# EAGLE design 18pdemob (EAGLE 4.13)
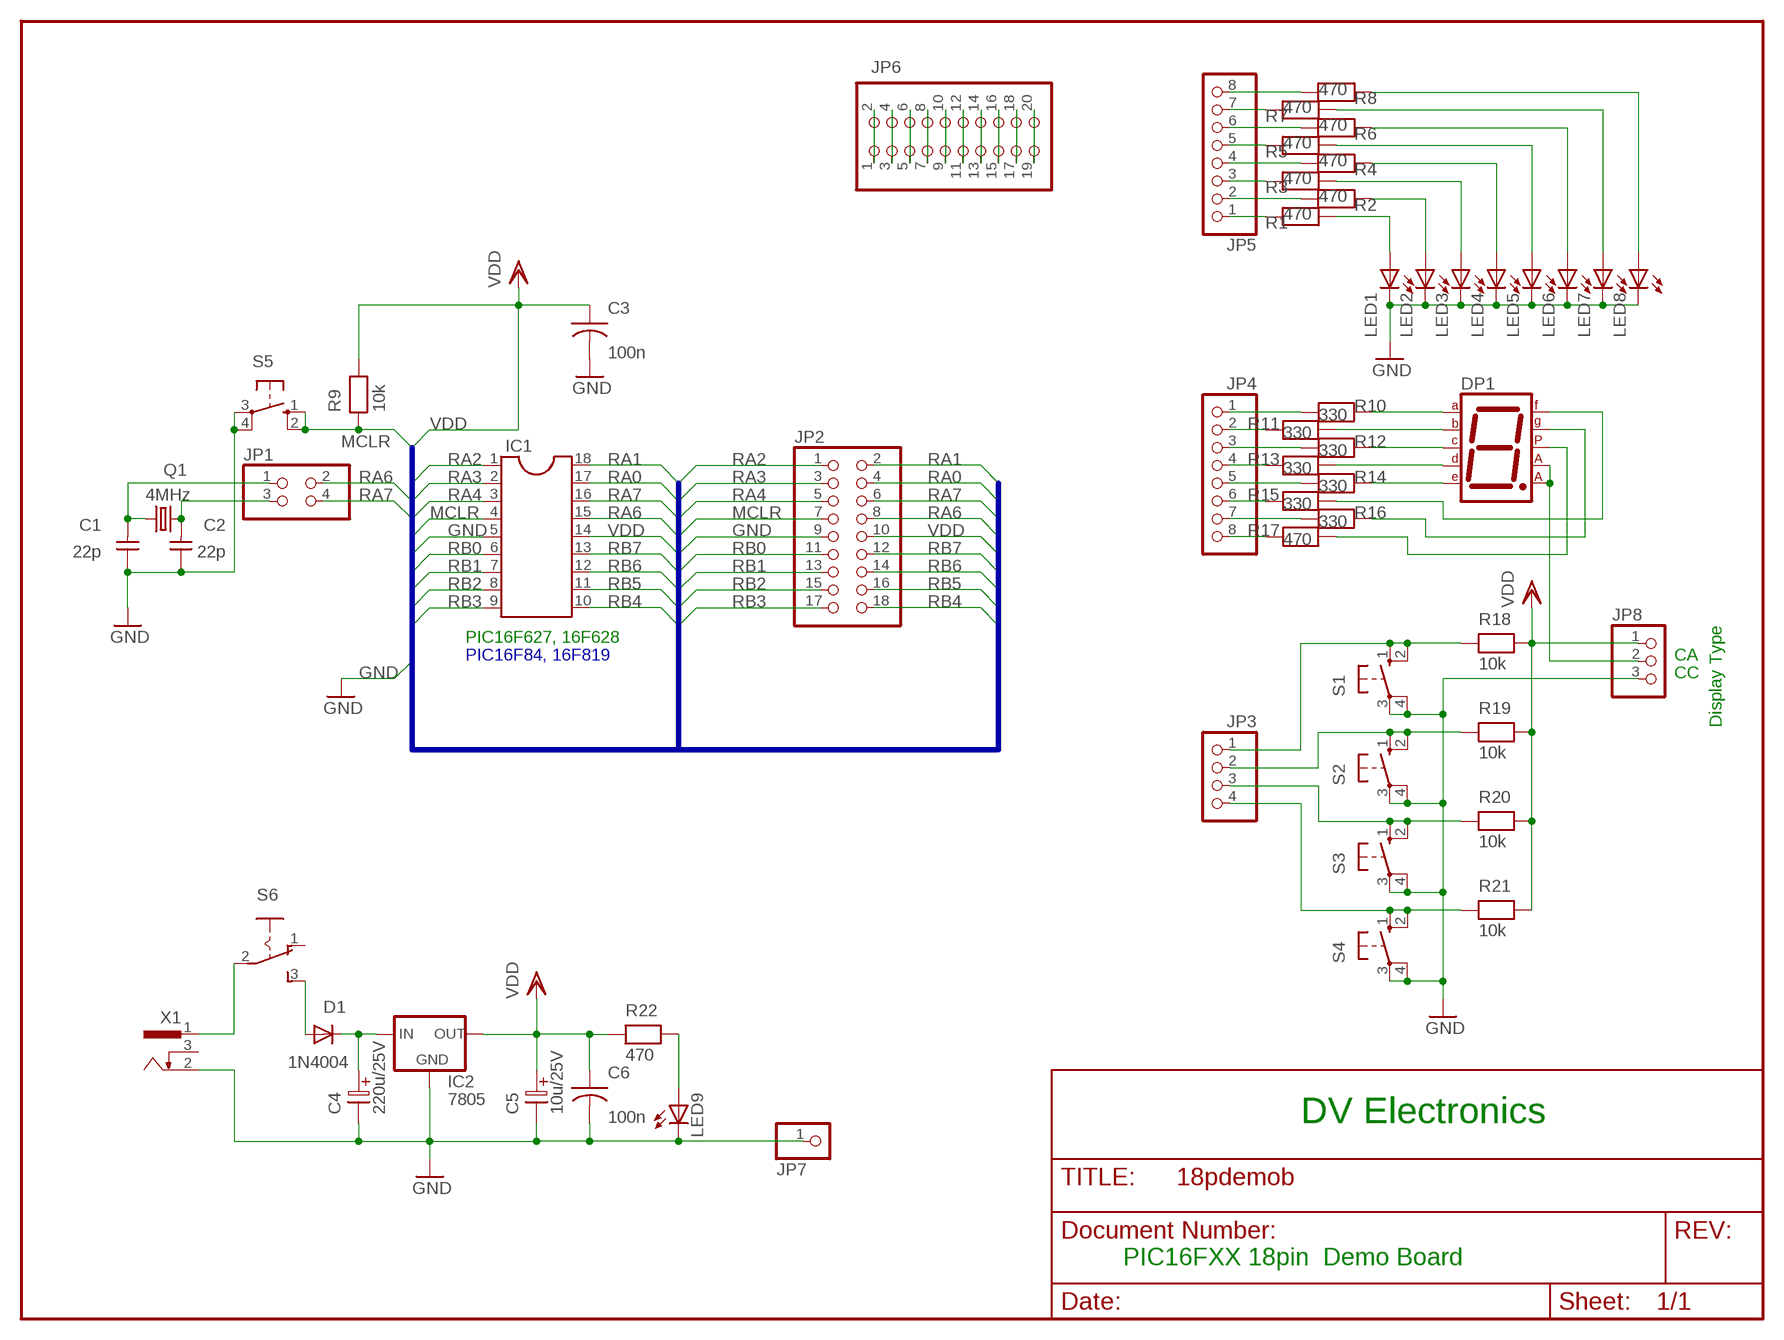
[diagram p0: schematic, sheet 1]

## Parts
C1  22p  CAPNP-5  [C-5]
C2  22p  CAPNP-5  [C-5]
C3  100n  CAP-5  [C-5]
C4  220u/25V  ELC-5  [ES-5]
C5  10u/25V  ELC-2,5L  [ES-2,5L]
C6  100n  CAP-5  [C-5]
D1  1N4004  [DO41-10]
DP1  7SEG-CA  [7SEG-13]
IC1  DIL18  [DIL18]
IC2  7805  78XXL  [78XXL]
JP1  PINHD-2X2  [2X02]
JP2  PINHD-2X9  [2X09]
JP3  PINHD-1X4  [1X04]
JP4  PINHD-1X8  [1X08]
JP5  PINHD-1X8  [1X08]
JP6  PINHD-2X10  [2X10]
JP7  PINHD-1X1  [1X01]
JP8  PINHD-1X3  [1X03]
LED1  LED3MM  [LED3MM]
LED2  LED3MM  [LED3MM]
LED3  LED3MM  [LED3MM]
LED4  LED3MM  [LED3MM]
LED5  LED3MM  [LED3MM]
LED6  LED3MM  [LED3MM]
LED7  LED3MM  [LED3MM]
LED8  LED3MM  [LED3MM]
LED9  LED3MM  [LED3MM]
Q1  4MHz  CRYTALHC49S  [HC49/S]
R1  470  RESEU-10  [R-10]
R2  470  RESEU-10  [R-10]
R3  470  RESEU-10  [R-10]
R4  470  RESEU-10  [R-10]
R5  470  RESEU-10  [R-10]
R6  470  RESEU-10  [R-10]
R7  470  RESEU-10  [R-10]
R8  470  RESEU-10  [R-10]
R9  10k  RESEU-10  [R-10]
R10  330  RESEU-7,5  [R-7,5]
R11  330  RESEU-7,5  [R-7,5]
R12  330  RESEU-7,5  [R-7,5]
R13  330  RESEU-7,5  [R-7,5]
R14  330  RESEU-7,5  [R-7,5]
R15  330  RESEU-7,5  [R-7,5]
R16  330  RESEU-7,5  [R-7,5]
R17  470  RESEU-7,5  [R-7,5]
R18  10k  RESEU-7,5  [R-7,5]
R19  10k  RESEU-7,5  [R-7,5]
R20  10k  RESEU-7,5  [R-7,5]
R21  10k  RESEU-7,5  [R-7,5]
R22  470  RESEU-7,5  [R-7,5]
S1  10-XX  [B3F-10XX]
S2  10-XX  [B3F-10XX]
S3  10-XX  [B3F-10XX]
S4  10-XX  [B3F-10XX]
S5  10-XX  [B3F-10XX]
S6  255SB  [255SB]
X1  SCD-014A  [SCD-014-A]

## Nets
GND: C1.1 C2.1 C3.2 C4.2 C5.2 C6.2 IC1.5 IC2.GND JP2.9 JP7.1 JP8.3 LED1.K(C) LED2.K(C) LED3.K(C) LED4.K(C) LED5.K(C) LED6.K(C) LED7.K(C) LED8.K(C) LED9.K(C) S1.3(P) S1.4(P1) S2.3(P) S2.4(P1) S3.3(P) S3.4(P1) S4.3(P) S4.4(P1) S5.3(P) S5.4(P1) X1.2
MCLR: IC1.4 JP2.7 R9.1 S5.1(S) S5.2(S1)
N$2: DP1.7(A) R10.2
N$3: DP1.6(B) R11.2
N$4: DP1.4(C) R12.2
N$5: DP1.2(D) R13.2
N$6: DP1.1(E) R14.2
N$7: DP1.9(F) R15.2
N$8: DP1.10(G) R16.2
N$9: LED1.A R1.2
N$10: LED2.A R2.2
N$11: LED3.A R3.2
N$12: LED4.A R4.2
N$13: LED5.A R5.2
N$14: LED6.A R6.2
N$15: LED7.A R7.2
N$16: LED8.A R8.2
N$20: C2.2 JP1.3 Q1.2
N$22: C1.2 JP1.1 Q1.1
N$24: JP5.8 R8.1
N$34: S6.2(P) X1.1
N$35: C4.1 D1.C IC2.IN
N$38: DP1.5(DP) R17.2
N$39: JP6.1 JP6.2
N$40: JP4.7 R16.1
N$41: JP4.5 R14.1
N$42: JP4.3 R12.1
N$43: JP4.1 R10.1
N$44: JP4.2 R11.1
N$45: JP4.4 R13.1
N$46: JP4.6 R15.1
N$47: JP4.8 R17.1
N$48: JP5.7 R7.1
N$49: JP5.6 R6.1
N$50: JP5.5 R5.1
N$51: JP5.4 R4.1
N$52: JP5.3 R3.1
N$53: JP5.2 R2.1
N$54: JP5.1 R1.1
N$220: DP1.3(CA1) DP1.8(CA2) JP8.2
N$383: LED9.A R22.2
N$384: JP3.1 R18.1 S1.1(S) S1.2(S1)
N$385: JP3.2 R19.1 S2.1(S) S2.2(S1)
N$386: JP3.3 R20.1 S3.1(S) S3.2(S1)
N$387: JP3.4 R21.1 S4.1(S) S4.2(S1)
N$390: JP6.3 JP6.4
N$391: JP6.5 JP6.6
N$392: JP6.7 JP6.8
N$393: JP6.9 JP6.10
N$394: JP6.11 JP6.12
N$395: JP6.13 JP6.14
N$396: JP6.15 JP6.16
N$397: JP6.17 JP6.18
N$398: JP6.19 JP6.20
N$399: D1.A S6.3(S)
RA0: IC1.17 JP2.4
RA1: IC1.18 JP2.2
RA2: IC1.1 JP2.1
RA3: IC1.2 JP2.3
RA4: IC1.3 JP2.5
RA6: IC1.15 JP1.2 JP2.8
RA7: IC1.16 JP1.4 JP2.6
RB0: IC1.6 JP2.11
RB1: IC1.7 JP2.13
RB2: IC1.8 JP2.15
RB3: IC1.9 JP2.17
RB4: IC1.10 JP2.18
RB5: IC1.11 JP2.16
RB6: IC1.12 JP2.14
RB7: IC1.13 JP2.12
VDD: C3.1 C5.1 C6.1 IC1.14 IC2.OUT JP2.10 JP8.1 R9.2 R18.2 R19.2 R20.2 R21.2 R22.1
Unconnected: S6.1(O) X1.3

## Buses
B$1

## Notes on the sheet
- Display Type
- PIC16F627, 16F628
- PIC16F84, 16F819 | CA
- CC
- DV Electronics
- PIC16FXX 18pin  Demo Board

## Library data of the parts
C1 C2 = discrete:CAPNP-5
C3 C6 = discrete:CAP-5
C4 = discrete:ELC-5
C5 = discrete:ELC-2,5L
D1 = diode:1N4004: DIODE
DP1 = special:7SEG-CA: 7-segment DISPLAY single anode, 13 mm
IC1 = ic-package:DIL18: Dual In Line
IC2 = v-reg:78XXL: VOLTAGE REGULATOR
JP1 = pinhead:PINHD-2X2: PIN HEADER
JP2 = pinhead:PINHD-2X9: PIN HEADER
JP3 = pinhead:PINHD-1X4: PIN HEADER
JP4 JP5 = pinhead:PINHD-1X8: PIN HEADER
JP6 = pinhead:PINHD-2X10: PIN HEADER
JP7 = pinhead:PINHD-1X1: PIN HEADER
JP8 = pinhead:PINHD-1X3: PIN HEADER
LED1-LED9 = led:LED: LED
Q1 = crystal:CRYTAL: CRYSTAL
R1-R9 = discrete:RESEU-10
R10-R22 = discrete:RESEU-7,5
S1-S5 = switch-omron:10-XX: OMRON SWITCH
S6 = switch:255SB: SLIDING SWITCH distributor Buerklin, 11G810
X1 = con-shiua-chyuan:SCD-014A: Power Jack 2.5mm

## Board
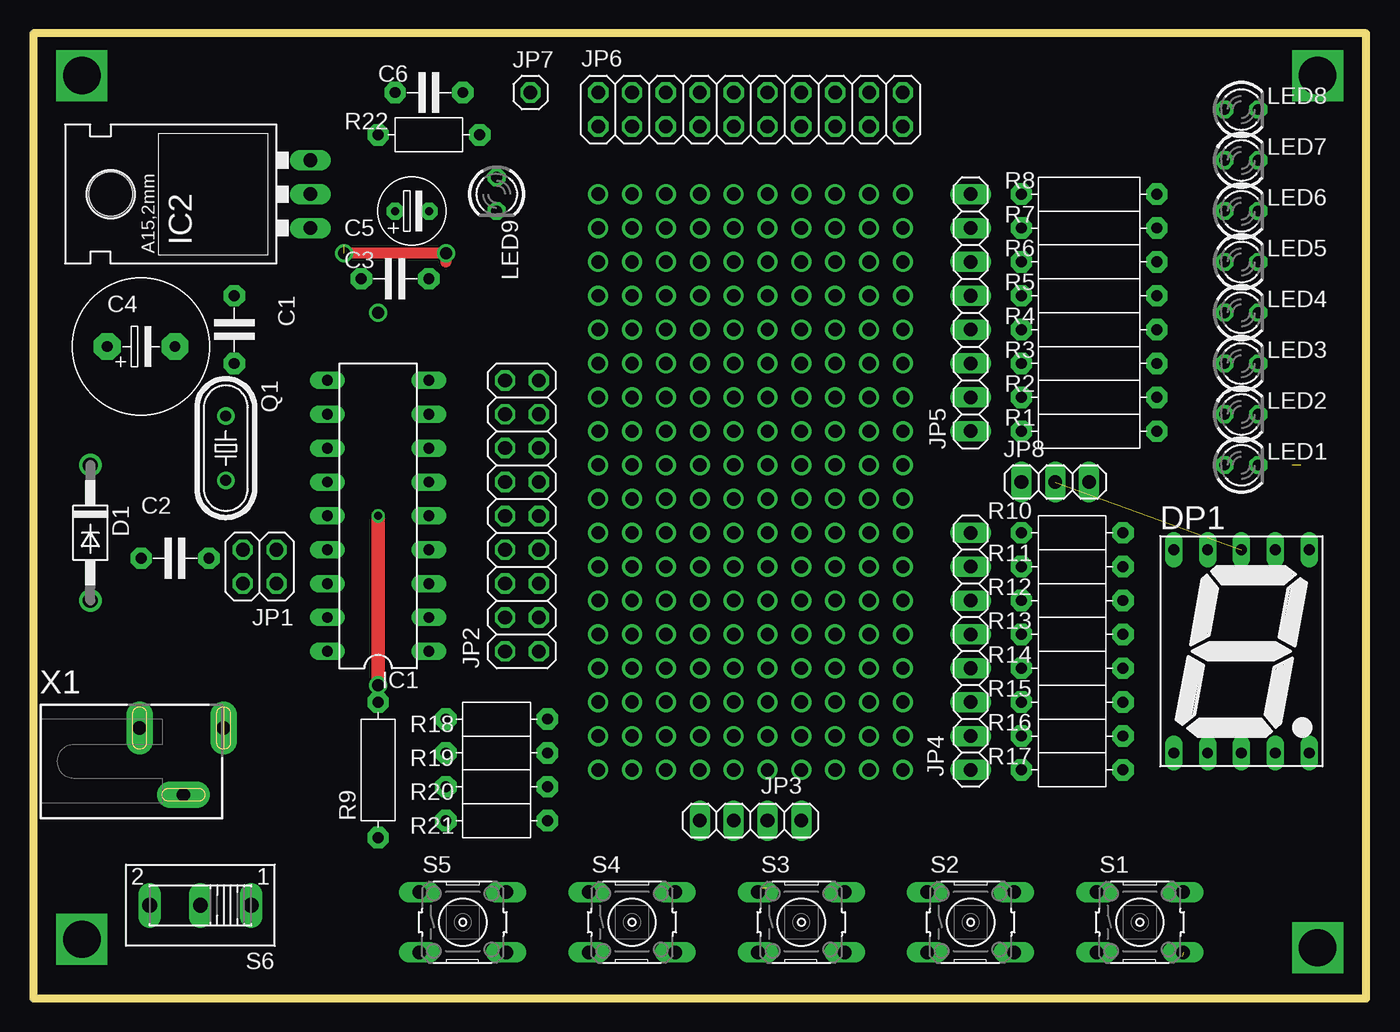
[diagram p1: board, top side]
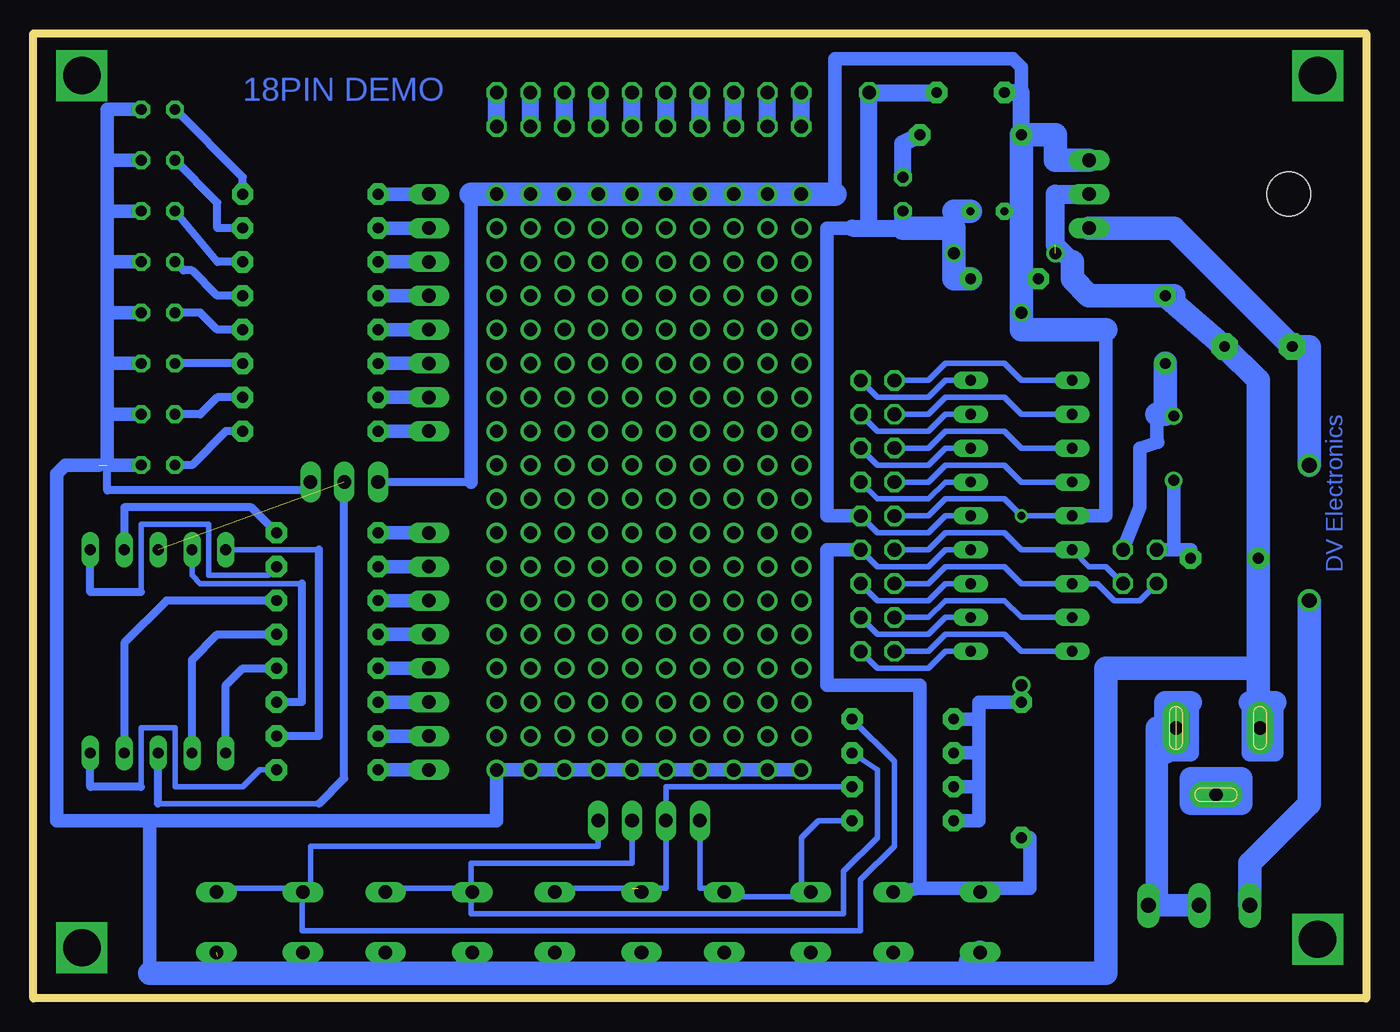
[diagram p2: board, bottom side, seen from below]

Size 100 x 72.38 mm. Coordinates in mm from the lower left corner, seen from the top.
Outline: 0,0 100,0 100,72.38 0,72.38 0,0
Copper layers (1*16): Top 0.035mm / dielectric 1.5mm / Bottom 0.035mm
Design rules "default": minimum track width 10mil, minimum drill 24mil, track to track 8mil, track to pad 8mil, pad to pad 8mil, via to via 8mil, smd to smd 8mil, copper to edge 40mil, drill to drill 8mil, minimum pad ring 10mil, minimum via ring 8mil, stop-mask expansion 4mil, vias tented up to drill 0mil, thermal gap 10mil

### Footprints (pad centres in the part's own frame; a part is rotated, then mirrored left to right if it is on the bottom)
C-5 = drill 0.813 pad 1.6 octagon: 1 -2.54,0; 2 2.54,0
ES-5 = drill 0.813 pad 2.007 octagon: 1 -2.54,0; 2 2.54,0
ES-2,5L = drill 0.61 pad 1.27 octagon: 1 0,0; 2 2.54,0
DO41-10 = drill 1.118 round: A 5.08,0; C -5.08,0
7SEG-13 = drill 0.813 long: 1 -5.08,-7.62; 2 -2.54,-7.62; 3 0,-7.62; 4 2.54,-7.62; 5 5.08,-7.62; 6 5.08,7.62; 7 2.54,7.62; 8 0,7.62; 9 -2.54,7.62; 10 -5.08,7.62
DIL18 = drill 0.813 long: 1 -10.16,-3.81; 2 -7.62,-3.81; 3 -5.08,-3.81; 4 -2.54,-3.81; 5 0,-3.81; 6 2.54,-3.81; 7 5.08,-3.81; 8 7.62,-3.81; 9 10.16,-3.81; 10 10.16,3.81; 11 7.62,3.81; 12 5.08,3.81; 13 2.54,3.81; 14 0,3.81; 15 -2.54,3.81; 16 -5.08,3.81; 17 -7.62,3.81; 18 -10.16,3.81
78XXL = drill 1.016 long: GND 0,-3.81; IN -2.54,-3.81; OUT 2.54,-3.81 | hole 3.302: 0,11.176
2X02 = drill 1.016 octagon: 1 -1.27,-1.27; 2 -1.27,1.27; 3 1.27,-1.27; 4 1.27,1.27
2X09 = drill 1.016 octagon: 1 -10.16,-1.27; 2 -10.16,1.27; 3 -7.62,-1.27; 4 -7.62,1.27; 5 -5.08,-1.27; 6 -5.08,1.27; 7 -2.54,-1.27; 8 -2.54,1.27; 9 0,-1.27; 10 0,1.27; 11 2.54,-1.27; 12 2.54,1.27; 13 5.08,-1.27; 14 5.08,1.27; 15 7.62,-1.27; 16 7.62,1.27; 17 10.16,-1.27; 18 10.16,1.27
1X04 = drill 1.016 long: 1 -3.81,0; 2 -1.27,0; 3 1.27,0; 4 3.81,0
1X08 = drill 1.016 long: 1 -8.89,0; 2 -6.35,0; 3 -3.81,0; 4 -1.27,0; 5 1.27,0; 6 3.81,0; 7 6.35,0; 8 8.89,0
2X10 = drill 1.016 octagon: 1 -11.43,-1.27; 2 -11.43,1.27; 3 -8.89,-1.27; 4 -8.89,1.27; 5 -6.35,-1.27; 6 -6.35,1.27; 7 -3.81,-1.27; 8 -3.81,1.27; 9 -1.27,-1.27; 10 -1.27,1.27; 11 1.27,-1.27; 12 1.27,1.27; 13 3.81,-1.27; 14 3.81,1.27; 15 6.35,-1.27; 16 6.35,1.27; 17 8.89,-1.27; 18 8.89,1.27; 19 11.43,-1.27; 20 11.43,1.27
1X01 = drill 1.016 octagon: 1 0,0
1X03 = drill 1.016 long: 1 -2.54,0; 2 0,0; 3 2.54,0
LED3MM = drill 0.813 octagon: A -1.27,0; K 1.27,0
HC49/S = drill 0.813 round: 1 -2.413,0; 2 2.413,0
R-10 = drill 0.813 pad 1.6 octagon: 1 -5.08,0; 2 5.08,0
R-7,5 = drill 0.813 pad 1.6 octagon: 1 -3.81,0; 2 3.81,0
B3F-10XX = drill 1.016 long: 1 -3.251,2.261; 2 3.251,2.261; 3 -3.251,-2.261; 4 3.251,-2.261
255SB = drill 1.118 long: 1 -3.81,0; 2 0,0; 3 3.81,0
SCD-014-A = drill 1 pad 2 long: 1 -2.5,13.8; 2 -2.5,7.5; 3 2.5,10.8

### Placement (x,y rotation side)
C1  15.08,50.16 270 top
C2  10.63,33.02 0 top
C3  27.14,53.97 0 top
C4  8.09,48.89 0 top
C5  27.14,59.05 0 top
C6  29.68,67.94 0 top
D1  4.28,34.92 270 top
DP1  90.64,26.03 0 top
IC1  25.87,36.19 90 top
IC2  16.98,60.32 90 top
JP1  16.98,32.38 180 top
JP2  36.66,36.19 90 top
JP3  53.81,13.33 180 top
JP4  70.32,26.03 270 top
JP5  70.32,51.43 90 top
JP6  53.81,66.67 0 top
JP7  37.3,67.94 0 top
JP8  76.67,38.73 0 top
LED1  90.64,40 0 top
LED2  90.64,43.81 0 top
LED3  90.64,47.62 0 top
LED4  90.64,51.43 0 top
LED5  90.64,55.24 0 top
LED6  90.64,59.05 0 top
LED7  90.64,62.86 0 top
LED8  90.64,66.67 0 top
LED9  34.76,60.32 270 top
Q1  14.44,41.27 270 top
R1  79.21,42.54 0 top
R2  79.21,45.08 0 top
R3  79.21,47.62 0 top
R4  79.21,50.16 0 top
R5  79.21,52.7 0 top
R6  79.21,55.24 0 top
R7  79.21,57.78 0 top
R8  79.21,60.32 0 top
R9  25.87,17.14 90 top
R10  77.94,34.92 0 top
R11  77.94,32.38 0 top
R12  77.94,29.84 0 top
R13  77.94,27.3 0 top
R14  77.94,24.76 0 top
R15  77.94,22.22 0 top
R16  77.94,19.68 0 top
R17  77.94,17.14 0 top
R18  34.76,20.95 180 top
R19  34.76,18.41 180 top
R20  34.76,15.87 180 top
R21  34.76,13.33 180 top
R22  29.68,64.77 0 top
S1  83.02,5.71 0 top
S2  70.32,5.71 0 top
S3  57.62,5.71 0 top
S4  44.92,5.71 0 top
S5  32.22,5.71 0 top
S6  12.54,6.98 180 top
X1  0.47,17.77 270 top

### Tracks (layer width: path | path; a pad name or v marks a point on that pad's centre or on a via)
GND  (via drill 0.9, 1)  (3 unrouted)
  Top 0.813: 30.95,55.24 v30.95,55.88 v23.33,55.88
  Bottom 0.406: 30.95,57.78 30.95,59.05 | IC1.5 31.58,36.19 32.85,34.92 36.66,34.92 JP2.9
  Bottom 0.61: JP8.3 79.84,38.1 94.45,38.1 94.45,40
  Bottom 1.016: 86.83,3.17 85.56,1.9 86.19,2.54 86.19,3.17 | S1.3 80.48,2.74 80.48,1.9 | S2.4 74.13,2.89 74.13,1.9 | S2.3 67.78,2.74 67.78,1.9 | S3.4 61.43,2.89 61.43,1.9 | S3.3 55.08,2.74 55.08,1.9 | S4.4 48.73,2.89 48.73,1.9 | S4.3 42.38,2.74 42.38,1.9 | S5.4 36.03,2.89 36.03,1.9 | 29.68,1.9 29.68,2.74 | v42.38,17.14 v65.24,17.14 65.24,13.33 91.28,13.33 | 91.28,1.9 91.28,13.33 | 91.28,13.33 98.26,13.33 98.26,39.37 97.62,40 95.08,40 | LED8.K 94.45,66.67 94.45,62.86 | 94.45,43.81 94.45,40 LED1.K | 94.45,43.81 94.45,47.62 | 94.45,47.62 94.45,51.43 | 94.45,51.43 94.45,55.24 | 94.45,55.24 94.45,59.05 | 94.45,59.05 94.45,62.86 | 94.45,62.86 LED7.K | 94.45,59.05 LED6.K | 94.45,55.24 LED5.K | 94.45,51.43 LED4.K | 94.45,47.62 LED3.K | 94.45,43.81 LED2.K | JP2.9 40.48,36.19 40.48,57.78 38.57,57.78
  Bottom 1.27: 37.3,57.78 JP7.1 C6.2 | 37.3,57.78 34.76,57.78 LED9.K | 38.57,57.78 37.3,57.78
  Bottom 1.422: C4.2 C1.1 | 22.06,55.24 23.33,56.51 23.33,60.32 IC2.GND
  Bottom 1.676: X1.2 8.09,20.27 8.09,20.31 8.09,19.68
  Bottom 1.778: 34.76,57.78 30.95,57.78 v30.95,55.88 30.95,53.97 C3.2 | 30.95,59.05 C5.2 | C1.1 14.44,52.7 | C1.1 20.79,52.7 22.06,53.97 22.06,55.24 | 29.68,2.74 S5.3 | 91.28,1.9 85.56,1.9 80.48,1.9 74.13,1.9 67.78,1.9 61.43,1.9 55.08,1.9 48.73,1.9 42.38,1.9 36.03,1.9 29.68,1.9 19.52,1.9 19.52,24.76 8.09,24.76 | 8.09,24.76 C2.1 8.09,46.35 C4.2 C1.1 | 8.09,24.76 8.09,20.31
MCLR
  Bottom 0.406: JP2.7 36.66,32.38 32.85,32.38 31.58,33.65 IC1.4 | 25.23,8.25 33.49,8.25
  Bottom 1.016: 33.49,8.25 S5.2 | 33.49,8.25 29.04,8.25 S5.1 28.69,8.25 25.23,8.25 25.23,12.06 R9.1 | JP2.7 40.48,33.65 40.48,23.49 33.49,23.49 33.49,8.25
N$1  (via drill 1)
  other vias: 42.38,60.32
N$2
  Bottom 0.61: DP1.7 93.18,36.83 83.66,36.83 R10.2
N$3
  Bottom 0.406: R11.2 82.39,31.74 86.83,31.74 86.83,35.55 91.91,35.55 91.91,30.47
  Bottom 0.61: 91.91,30.47 95.72,30.47 DP1.6
N$4
  Bottom 0.61: DP1.4 93.18,26.66 90,29.84 R12.2
N$5
  Bottom 0.61: R13.2 86.19,27.3 88.1,25.39 DP1.2
N$6
  Bottom 0.61: R14.2 84.29,24.76 85.56,23.49 DP1.1
N$7
  Bottom 0.406: DP1.9 88.1,31.74 87.47,31.11 79.84,31.11
  Bottom 0.61: 79.84,31.11 79.84,22.22 R15.2
N$8
  Bottom 0.406: 78.58,33.65 DP1.10
  Bottom 0.61: R16.2 78.58,19.68 78.58,33.65
N$9
  Bottom 0.61: LED1.A 88.1,40 85.56,42.54 R1.2
N$10
  Bottom 0.61: LED2.A 87.47,43.81 86.19,45.08 R2.2
N$11
  Bottom 0.61: R3.2 LED3.A
N$12
  Bottom 0.61: LED4.A 87.47,51.43 86.19,50.16 R4.2
N$13
  Bottom 0.61: LED5.A 88.73,54.61 88.1,54.61 86.19,52.7 R5.2
N$14
  Bottom 0.61: LED6.A 86.19,55.24 R6.2
N$15
  Bottom 0.61: LED7.A 86.19,59.69 86.19,57.78 R7.2
N$16
  Bottom 0.61: LED8.A 84.29,61.59 R8.2
N$17  (via drill 1)
  other vias: 44.92,60.32
N$18  (via drill 1)
  other vias: 47.46,60.32
N$19  (via drill 1)
  other vias: 50,60.32
N$20
  Bottom 0.406: JP1.3 14.44,33.65
  Bottom 1.016: 14.44,33.65 Q1.2 | JP1.3 13.17,33.65 C2.2
N$21  (via drill 1)
  other vias: 52.54,60.32
N$22
  Bottom 0.406: 14.44,43.81 Q1.1 | 15.65,41.71 15.71,41.91
  Bottom 1.016: JP1.1 16.98,36.83 16.98,41.27 15.65,41.71 | 15.71,41.91 15.71,43.81 14.44,43.81
  Bottom 1.778: 15.71,43.81 15.08,43.81 C1.2
N$23  (via drill 1)
  other vias: 55.08,60.32
N$24
  Bottom 1.016: JP5.8 R8.1
N$25  (via drill 1)
  other vias: 57.62,60.32
N$26  (via drill 1)
  other vias: 60.16,60.32
N$27  (via drill 1)
  other vias: 62.7,60.32
N$28  (via drill 1)
  other vias: 65.24,60.32
N$29  (via drill 1)
  other vias: 42.38,57.78
N$30  (via drill 1)
  other vias: 44.92,57.78
N$31  (via drill 1)
  other vias: 47.46,57.78
N$32  (via drill 1)
  other vias: 50,57.78
N$33  (via drill 1)
  other vias: 52.54,57.78
N$34
  Bottom 1.676: S6.2 15.71,6.98 15.71,20.27 | X1.1 15.71,20.27 | 15.71,20.27 15.71,20.31
N$35
  Bottom 1.778: IC2.IN 14.44,57.78 C4.1 4.28,48.89 D1.C
N$36  (via drill 1)
  other vias: 55.08,57.78
N$37  (via drill 1)
  other vias: 57.62,57.78
N$38
  Bottom 0.406: 91.91,15.87 91.91,20.31 89.37,20.31 89.37,15.87 84.29,15.87 83.02,17.14 R17.2
  Bottom 0.61: DP1.5 95.72,15.87 91.91,15.87
N$39
  Bottom 1.27: JP6.1 JP6.2
N$40
  Bottom 1.016: JP4.7 R16.1
N$41
  Bottom 1.016: JP4.5 R14.1
N$42
  Bottom 1.016: JP4.3 R12.1
N$43
  Bottom 1.016: JP4.1 R10.1
N$44
  Bottom 1.016: JP4.2 R11.1
N$45
  Bottom 1.016: JP4.4 R13.1
N$46
  Bottom 1.016: JP4.6 R15.1
N$47
  Bottom 1.016: JP4.8 R17.1
N$48
  Bottom 1.016: JP5.7 R7.1
N$49
  Bottom 1.016: JP5.6 R6.1
N$50
  Bottom 1.016: JP5.5 R5.1
N$51
  Bottom 1.016: JP5.4 R4.1
N$52
  Bottom 1.016: JP5.3 R3.1
N$53
  Bottom 1.016: JP5.2 R2.1
N$54
  Bottom 1.016: JP5.1 R1.1
N$55  (via drill 1)
  other vias: 60.16,57.78
N$56  (via drill 1)
  other vias: 62.7,57.78
N$57  (via drill 1)
  other vias: 65.24,57.78
N$58  (via drill 1)
  other vias: 42.38,55.24
N$59  (via drill 1)
  other vias: 44.92,55.24
N$60  (via drill 1)
  other vias: 47.46,55.24
N$61  (via drill 1)
  other vias: 50,55.24
N$62  (via drill 1)
  other vias: 52.54,55.24
N$63  (via drill 1)
  other vias: 55.08,55.24
N$64  (via drill 1)
  other vias: 57.62,55.24
N$65  (via drill 1)
  other vias: 60.16,55.24
N$66  (via drill 1)
  other vias: 62.7,55.24
N$67  (via drill 1)
  other vias: 65.24,55.24
N$68  (via drill 1)
  other vias: 42.38,52.7
N$69  (via drill 1)
  other vias: 44.92,52.7
N$70  (via drill 1)
  other vias: 47.46,52.7
N$71  (via drill 1)
  other vias: 50,52.7
N$72  (via drill 1)
  other vias: 52.54,52.7
N$73  (via drill 1)
  other vias: 55.08,52.7
N$74  (via drill 1)
  other vias: 57.62,52.7
N$75  (via drill 1)
  other vias: 60.16,52.7
N$76  (via drill 1)
  other vias: 62.7,52.7
N$77  (via drill 1)
  other vias: 65.24,52.7
N$78  (via drill 1)
  other vias: 42.38,50.16
N$79  (via drill 1)
  other vias: 44.92,50.16
N$80  (via drill 1)
  other vias: 47.46,50.16
N$81  (via drill 1)
  other vias: 50,50.16
N$82  (via drill 1)
  other vias: 52.54,50.16
N$83  (via drill 1)
  other vias: 55.08,50.16
N$84  (via drill 1)
  other vias: 57.62,50.16
N$85  (via drill 1)
  other vias: 60.16,50.16
N$86  (via drill 1)
  other vias: 62.7,50.16
N$87  (via drill 1)
  other vias: 65.24,50.16
N$88  (via drill 1)
  other vias: 42.38,47.62
N$89  (via drill 1)
  other vias: 44.92,47.62
N$90  (via drill 1)
  other vias: 47.46,47.62
N$91  (via drill 1)
  other vias: 50,47.62
N$92  (via drill 1)
  other vias: 52.54,47.62
N$93  (via drill 1)
  other vias: 55.08,47.62
N$94  (via drill 1)
  other vias: 57.62,47.62
N$95  (via drill 1)
  other vias: 60.16,47.62
N$96  (via drill 1)
  other vias: 62.7,47.62
N$97  (via drill 1)
  other vias: 65.24,47.62
N$98  (via drill 1)
  other vias: 42.38,45.08
N$99  (via drill 1)
  other vias: 44.92,45.08
N$100  (via drill 1)
  other vias: 47.46,45.08
N$101  (via drill 1)
  other vias: 50,45.08
N$102  (via drill 1)
  other vias: 52.54,45.08
N$103  (via drill 1)
  other vias: 55.08,45.08
N$104  (via drill 1)
  other vias: 57.62,45.08
N$105  (via drill 1)
  other vias: 60.16,45.08
N$106  (via drill 1)
  other vias: 62.7,45.08
N$107  (via drill 1)
  other vias: 65.24,45.08
N$108  (via drill 1)
  other vias: 42.38,42.54
N$109  (via drill 1)
  other vias: 44.92,42.54
N$110  (via drill 1)
  other vias: 47.46,42.54
N$111  (via drill 1)
  other vias: 50,42.54
N$112  (via drill 1)
  other vias: 52.54,42.54
N$113  (via drill 1)
  other vias: 55.08,42.54
N$114  (via drill 1)
  other vias: 57.62,42.54
N$115  (via drill 1)
  other vias: 60.16,42.54
N$116  (via drill 1)
  other vias: 62.7,42.54
N$117  (via drill 1)
  other vias: 65.24,42.54
N$118  (via drill 1)
  other vias: 42.38,40
N$119  (via drill 1)
  other vias: 44.92,40
N$120  (via drill 1)
  other vias: 47.46,40
N$121  (via drill 1)
  other vias: 50,40
N$122  (via drill 1)
  other vias: 52.54,40
N$123  (via drill 1)
  other vias: 55.08,40
N$124  (via drill 1)
  other vias: 57.62,40
N$125  (via drill 1)
  other vias: 60.16,40
N$126  (via drill 1)
  other vias: 62.7,40
N$127  (via drill 1)
  other vias: 65.24,40
N$128  (via drill 1)
  other vias: 42.38,37.46
N$129  (via drill 1)
  other vias: 44.92,37.46
N$130  (via drill 1)
  other vias: 47.46,37.46
N$131  (via drill 1)
  other vias: 50,37.46
N$132  (via drill 1)
  other vias: 52.54,37.46
N$133  (via drill 1)
  other vias: 55.08,37.46
N$134  (via drill 1)
  other vias: 57.62,37.46
N$135  (via drill 1)
  other vias: 60.16,37.46
N$136  (via drill 1)
  other vias: 62.7,37.46
N$137  (via drill 1)
  other vias: 65.24,37.46
N$138  (via drill 1)
  other vias: 42.38,34.92
N$139  (via drill 1)
  other vias: 44.92,34.92
N$140  (via drill 1)
  other vias: 47.46,34.92
N$141  (via drill 1)
  other vias: 50,34.92
N$142  (via drill 1)
  other vias: 52.54,34.92
N$143  (via drill 1)
  other vias: 55.08,34.92
N$144  (via drill 1)
  other vias: 57.62,34.92
N$145  (via drill 1)
  other vias: 60.16,34.92
N$146  (via drill 1)
  other vias: 62.7,34.92
N$147  (via drill 1)
  other vias: 65.24,34.92
N$148  (via drill 1)
  other vias: 42.38,32.38
N$149  (via drill 1)
  other vias: 44.92,32.38
N$150  (via drill 1)
  other vias: 47.46,32.38
N$151  (via drill 1)
  other vias: 50,32.38
N$152  (via drill 1)
  other vias: 52.54,32.38
N$153  (via drill 1)
  other vias: 55.08,32.38
N$154  (via drill 1)
  other vias: 57.62,32.38
N$155  (via drill 1)
  other vias: 60.16,32.38
N$156  (via drill 1)
  other vias: 62.7,32.38
N$157  (via drill 1)
  other vias: 65.24,32.38
N$158  (via drill 1)
  other vias: 42.38,29.84
N$159  (via drill 1)
  other vias: 44.92,29.84
N$160  (via drill 1)
  other vias: 47.46,29.84
N$161  (via drill 1)
  other vias: 50,29.84
N$162  (via drill 1)
  other vias: 52.54,29.84
N$163  (via drill 1)
  other vias: 55.08,29.84
N$164  (via drill 1)
  other vias: 57.62,29.84
N$165  (via drill 1)
  other vias: 60.16,29.84
N$166  (via drill 1)
  other vias: 62.7,29.84
N$167  (via drill 1)
  other vias: 65.24,29.84
N$168  (via drill 1)
  other vias: 42.38,27.3
N$169  (via drill 1)
  other vias: 44.92,27.3
N$170  (via drill 1)
  other vias: 47.46,27.3
N$171  (via drill 1)
  other vias: 50,27.3
N$172  (via drill 1)
  other vias: 52.54,27.3
N$173  (via drill 1)
  other vias: 55.08,27.3
N$174  (via drill 1)
  other vias: 57.62,27.3
N$175  (via drill 1)
  other vias: 60.16,27.3
N$176  (via drill 1)
  other vias: 62.7,27.3
N$177  (via drill 1)
  other vias: 65.24,27.3
N$178  (via drill 1)
  other vias: 42.38,24.76
N$179  (via drill 1)
  other vias: 44.92,24.76
N$180  (via drill 1)
  other vias: 47.46,24.76
N$181  (via drill 1)
  other vias: 50,24.76
N$182  (via drill 1)
  other vias: 52.54,24.76
N$183  (via drill 1)
  other vias: 55.08,24.76
N$184  (via drill 1)
  other vias: 57.62,24.76
N$185  (via drill 1)
  other vias: 60.16,24.76
N$186  (via drill 1)
  other vias: 62.7,24.76
N$187  (via drill 1)
  other vias: 65.24,24.76
N$188  (via drill 1)
  other vias: 42.38,22.22
N$189  (via drill 1)
  other vias: 44.92,22.22
N$190  (via drill 1)
  other vias: 47.46,22.22
N$191  (via drill 1)
  other vias: 50,22.22
N$192  (via drill 1)
  other vias: 52.54,22.22
N$193  (via drill 1)
  other vias: 55.08,22.22
N$194  (via drill 1)
  other vias: 57.62,22.22
N$195  (via drill 1)
  other vias: 60.16,22.22
N$196  (via drill 1)
  other vias: 62.7,22.22
N$197  (via drill 1)
  other vias: 65.24,22.22
N$198  (via drill 1)
  other vias: 42.38,19.68
N$199  (via drill 1)
  other vias: 44.92,19.68
N$200  (via drill 1)
  other vias: 47.46,19.68
N$201  (via drill 1)
  other vias: 50,19.68
N$202  (via drill 1)
  other vias: 52.54,19.68
N$203  (via drill 1)
  other vias: 55.08,19.68
N$204  (via drill 1)
  other vias: 57.62,19.68
N$205  (via drill 1)
  other vias: 60.16,19.68
N$206  (via drill 1)
  other vias: 62.7,19.68
N$207  (via drill 1)
  other vias: 65.24,19.68
N$208  (via drill 2.8)
  other vias: 3.64,69.21
N$209  (via drill 1)
  other vias: 44.92,17.14
N$210  (via drill 1)
  other vias: 47.46,17.14
N$211  (via drill 1)
  other vias: 50,17.14
N$212  (via drill 1)
  other vias: 52.54,17.14
N$213  (via drill 1)
  other vias: 55.08,17.14
N$214  (via drill 1)
  other vias: 57.62,17.14
N$215  (via drill 1)
  other vias: 60.16,17.14
N$216  (via drill 1)
  other vias: 62.7,17.14
N$217  (via drill 2.8)
  other vias: 96.36,69.21
N$218  (via drill 2.8)
  other vias: 96.36,3.8
N$219  (via drill 2.8)
  other vias: 3.64,4.44
N$220  (1 unrouted)
  Bottom 0.406: 78.58,14.6 90.64,14.6
  Bottom 0.61: 90.64,14.6 DP1.3 | 78.58,14.6 76.67,16.5 JP8.2
N$221
  Bottom 1.27: 15.08,18.41 13.17,18.41 13.17,22.22
  Bottom 1.676: 13.17,22.22 15.08,22.22 15.08,18.41
N$222
  Bottom 1.676: 13.17,16.5 13.17,14.6 9.36,14.6 9.36,16.5 13.17,16.5
N$223
  Bottom 1.27: 8.73,21.58 8.73,18.41 6.82,18.41 6.82,22.22
  Bottom 1.676: 6.82,22.22 8.73,22.22
N$383
  Bottom 1.27: R22.2 34.76,64.13 LED9.A
N$384
  Bottom 0.406: R18.1 35.39,17.77 35.39,11.43 37.94,8.89 37.94,5.08 79.84,5.08 79.84,7.89 | 79.84,7.89 S1.1 | 79.84,7.89 79.21,8.53 79.21,11.43 57.62,11.43 JP3.1 | S1.2 86.19,8.05 86.19,8.25 80.2,8.25 79.84,7.89
N$385
  Bottom 0.406: R19.1 36.66,17.14 36.66,12.06 39.2,9.52 39.2,6.34 67.14,6.34 67.14,7.89 | 67.14,8.05 67.14,8.25 | 67.14,8.05 S2.1 67.14,7.89 | 67.14,7.89 67.14,8.05 | JP3.2 55.08,10.16 67.14,10.16 67.14,7.89 | S2.2 73.5,8.05 73.5,8.25 67.5,8.25 67.14,7.89
N$386  (1 unrouted)
  Bottom 0.406: 55.08,8.25 52.54,8.25 JP3.3 52.54,15.87 R20.1 | S3.2 60.8,8.05 60.8,8.25 54.65,8.25 S3.1
N$387
  Bottom 0.406: 50,8.25 JP3.4 | 50,8.25 48.73,8.25 | R21.1 41.11,13.33 42.38,12.06 42.38,8.25 41.74,8.25 | 41.74,8.25 41.11,8.25 | 50,8.25 48.45,8.25 S4.2 48.53,7.62 | 48.53,7.62 48.73,7.62 | 48.53,7.62 41.74,7.62 41.74,7.89 S4.1 41.74,8.05 41.74,8.25
N$390
  Bottom 1.27: JP6.3 JP6.4
N$391
  Bottom 1.27: JP6.5 JP6.6
N$392
  Bottom 1.27: JP6.7 JP6.8
N$393
  Bottom 1.27: JP6.9 JP6.10
N$394
  Bottom 1.27: JP6.11 JP6.12
N$395
  Bottom 1.27: JP6.13 JP6.14
N$396
  Bottom 1.27: JP6.15 JP6.16
N$397
  Bottom 1.27: JP6.17 JP6.18
N$398
  Bottom 1.27: JP6.19 JP6.20
N$399
  Bottom 1.778: D1.A 4.28,17.14 4.28,14.6 8.73,10.16 S6.3
RA0
  Bottom 0.406: JP2.4 32.85,28.57 31.58,29.84 27.14,29.84 25.87,28.57 IC1.17
RA1
  Bottom 0.406: JP2.2 32.85,26.03 31.58,27.3 27.14,27.3 25.87,26.03 IC1.18
RA2
  Bottom 0.406: JP2.1 36.66,24.76 32.85,24.76 31.58,26.03 IC1.1
RA3
  Bottom 0.406: JP2.3 36.66,27.3 32.85,27.3 31.58,28.57 IC1.2
RA4
  Bottom 0.406: JP2.5 36.66,29.84 32.85,29.84 31.58,31.11 IC1.3
RA6
  Bottom 0.406: JP2.8 32.85,33.65 31.58,34.92 27.14,34.92 25.87,33.65 IC1.15 20.79,32.38 19.52,32.38 JP1.2
RA7
  Bottom 0.406: JP2.6 32.85,31.11 31.58,32.38 27.14,32.38 25.87,31.11 IC1.16 20.15,31.11 18.88,29.84 16.98,29.84 JP1.4
RB0
  Bottom 0.406: JP2.11 36.66,37.46 32.85,37.46 31.58,38.73 IC1.6
RB1
  Bottom 0.406: JP2.13 36.66,40 32.85,40 31.58,41.27 IC1.7
RB2
  Bottom 0.406: JP2.15 36.66,42.54 32.85,42.54 31.58,43.81 IC1.8
RB3
  Bottom 0.406: JP2.17 36.66,45.08 32.85,45.08 31.58,46.35 IC1.9
RB4
  Bottom 0.406: JP2.18 32.85,46.35 31.58,47.62 27.14,47.62 25.87,46.35 IC1.10
RB5
  Bottom 0.406: JP2.16 32.85,43.81 31.58,45.08 27.14,45.08 25.87,43.81 IC1.11
RB6
  Bottom 0.406: JP2.14 32.85,41.27 31.58,42.54 27.14,42.54 25.87,41.27 IC1.12
RB7
  Bottom 0.406: JP2.12 32.85,38.73 31.58,40 27.14,40 25.87,38.73 IC1.13
VDD  (via drill 0.6, 0.9)
  Top 1.016: v25.87,23.49 v25.87,36.19
  Bottom 0.406: 25.87,53.97 C3.1 | 25.87,59.05 C5.1 | JP2.10 32.85,36.19 31.58,37.46 27.14,37.46 v25.87,36.19 IC1.14
  Bottom 0.61: 67.14,38.73 JP8.1
  Bottom 0.813: R9.2 v25.87,23.49
  Bottom 1.016: R21.2 29.04,13.33 29.04,15.87 | 29.04,15.87 29.04,18.41 | 29.04,18.41 29.04,20.95 | 29.04,20.95 R18.2 | R9.2 29.04,22.22 29.04,20.95 | 29.04,18.41 R19.2 | 29.04,15.87 R20.2 | 67.14,60.32 67.14,38.73 | 39.84,60.32 39.84,70.48 26.5,70.48 25.87,69.84 25.87,67.94 | 19.52,50.16 19.52,36.19 IC1.14
  Bottom 1.27: C6.1 25.87,67.94 R22.1
  Bottom 1.778: IC2.OUT 23.33,62.86 23.33,64.77 R22.1 25.87,59.05 25.87,53.97 v25.87,51.43 25.87,50.16 19.52,50.16 | 39.84,60.32 67.14,60.32

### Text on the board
Bottom: 18PIN DEMO | DV Electronics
